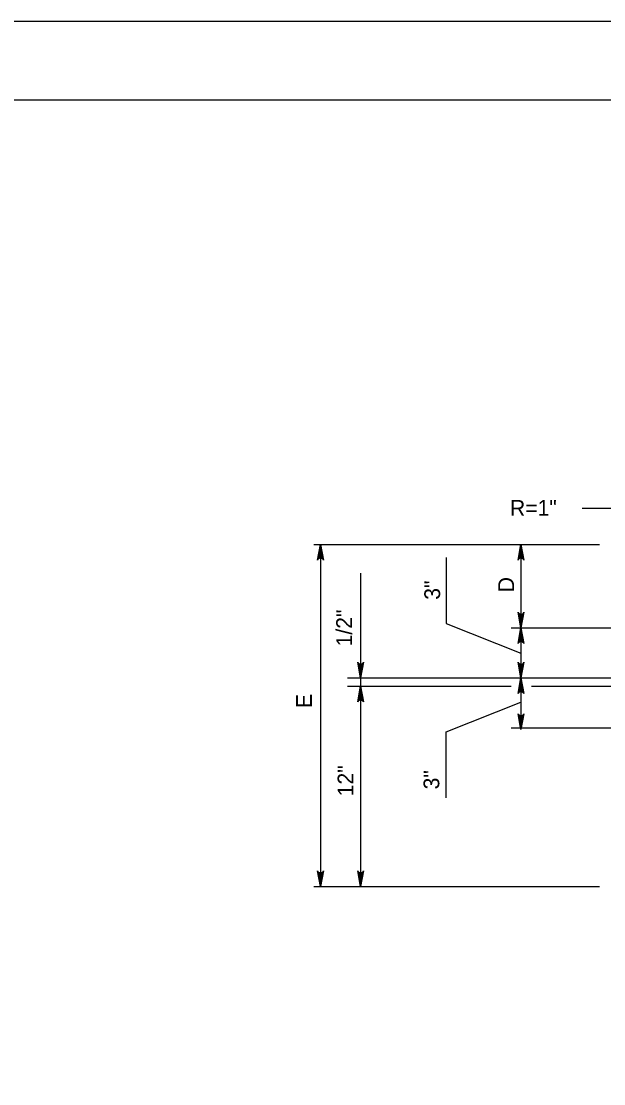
# Model space of a CAD drawing. Extents: x 2087776 to 2104538, y 970919 to 982612.
# Drawn here: x 2097196 to 2097559, y 981949 to 982612 of the extents above; entities that cross this region are included whole.
import ezdxf

# ---------------------------------------------------------------- set-up
doc = ezdxf.new("R2010")
doc.units = 0
doc.layers.add('1', color=7, linetype='Continuous')
doc.layers.add('PLT-BNDY', color=7, linetype='Continuous')

msp = doc.modelspace()

# ---------------------------------------------------------------- linework, layer by layer
at = {"layer": '1'}
for p, q in [((2097545.62, 982308.27), (2097566.97, 982308.27)), ((2097378.21, 982285.66), (2097556.45, 982285.66)), ((2097382.47, 982285.66), (2097382.47, 982072.11)), ((2097507.47, 982285.66), (2097507.47, 982171.07)), ((2097460.85, 982277.54), (2097460.85, 982236.2)), ((2097407.47, 982267.75), (2097407.47, 982072.11)), ((2097460.85, 982236.2), (2097507.47, 982217.8)), ((2097501.46, 982233.57), (2097633.63, 982233.57)), ((2097399.23, 982202.32), (2097633.63, 982202.32)), ((2097399.23, 982197.11), (2097501.46, 982197.11)), ((2097514.13, 982197.11), (2097633.63, 982197.11)), ((2097460.85, 982168.72), (2097507.47, 982187.12)), ((2097460.85, 982127.37), (2097460.85, 982168.72)), ((2097501.46, 982171.07), (2097607.78, 982171.07)), ((2097378.21, 982072.11), (2097556.45, 982072.11))]:
    msp.add_line(p, q, dxfattribs=at)
for points in [[(2098759.93, 980712.64), (2098759.93, 982563.04), (2096181.19, 982563.04), (2096181.19, 980712.64), (2098759.93, 980712.64), (2098759.93, 980799.12), (2098103.76, 980799.12), (2098103.76, 981011.32), (2098759.93, 981011.32), (2098759.93, 981106.34), (2098103.76, 981106.34), (2098103.76, 980712.64), (2098362.29, 980712.64), (2098362.29, 980799.12), (2098362.29, 980712.64), (2098614.92, 980712.64), (2098614.92, 980799.12), (2098614.92, 980758.72), (2098759.93, 980758.72)], [(2097382.47, 982285.66), (2097384.3, 982275.88), (2097384.04, 982276.25), (2097383.78, 982276.63), (2097383.45, 982276.82), (2097383.12, 982277.02), (2097382.8, 982277.07), (2097382.47, 982277.13), (2097382.14, 982277.07), (2097381.81, 982277.02), (2097381.48, 982276.82), (2097381.16, 982276.63), (2097380.89, 982276.25), (2097380.63, 982275.88), (2097382.47, 982285.66), (2097380.89, 982276.25), (2097381.16, 982276.63), (2097382.47, 982285.66), (2097381.48, 982276.82), (2097381.81, 982277.02), (2097382.47, 982285.66), (2097382.14, 982277.07), (2097382.47, 982277.13), (2097382.47, 982285.66), (2097382.8, 982277.07), (2097383.12, 982277.02), (2097382.47, 982285.66), (2097383.45, 982276.82), (2097383.78, 982276.63), (2097382.47, 982285.66), (2097384.04, 982276.25)], [(2097507.47, 982285.66), (2097509.3, 982275.88), (2097509.04, 982276.25), (2097508.78, 982276.63), (2097508.45, 982276.82), (2097508.12, 982277.02), (2097507.8, 982277.07), (2097507.47, 982277.13), (2097507.14, 982277.07), (2097506.81, 982277.02), (2097506.48, 982276.82), (2097506.16, 982276.63), (2097505.89, 982276.25), (2097505.63, 982275.88), (2097507.47, 982285.66), (2097505.89, 982276.25), (2097506.16, 982276.63), (2097507.47, 982285.66), (2097506.48, 982276.82), (2097506.81, 982277.02), (2097507.47, 982285.66), (2097507.14, 982277.07), (2097507.47, 982277.13), (2097507.47, 982285.66), (2097507.8, 982277.07), (2097508.12, 982277.02), (2097507.47, 982285.66), (2097508.45, 982276.82), (2097508.78, 982276.63), (2097507.47, 982285.66), (2097509.04, 982276.25)], [(2097507.47, 982233.57), (2097505.63, 982243.36), (2097505.89, 982242.98), (2097506.16, 982242.6), (2097506.48, 982242.41), (2097506.81, 982242.22), (2097507.14, 982242.16), (2097507.47, 982242.1), (2097507.8, 982242.16), (2097508.12, 982242.22), (2097508.45, 982242.41), (2097508.78, 982242.6), (2097509.04, 982242.98), (2097509.3, 982243.36), (2097507.47, 982233.57), (2097509.04, 982242.98), (2097508.78, 982242.6), (2097507.47, 982233.57), (2097508.45, 982242.41), (2097508.12, 982242.22), (2097507.47, 982233.57), (2097507.8, 982242.16), (2097507.47, 982242.1), (2097507.47, 982233.57), (2097507.14, 982242.16), (2097506.81, 982242.22), (2097507.47, 982233.57), (2097506.48, 982242.41), (2097506.16, 982242.6), (2097507.47, 982233.57), (2097505.89, 982242.98)], [(2097507.47, 982233.57), (2097509.3, 982223.79), (2097509.04, 982224.16), (2097508.78, 982224.54), (2097508.45, 982224.74), (2097508.12, 982224.93), (2097507.8, 982224.99), (2097507.47, 982225.04), (2097507.14, 982224.99), (2097506.81, 982224.93), (2097506.48, 982224.74), (2097506.16, 982224.54), (2097505.89, 982224.16), (2097505.63, 982223.79), (2097507.47, 982233.57), (2097505.89, 982224.16), (2097506.16, 982224.54), (2097507.47, 982233.57), (2097506.48, 982224.74), (2097506.81, 982224.93), (2097507.47, 982233.57), (2097507.14, 982224.99), (2097507.47, 982225.04), (2097507.47, 982233.57), (2097507.8, 982224.99), (2097508.12, 982224.93), (2097507.47, 982233.57), (2097508.45, 982224.74), (2097508.78, 982224.54), (2097507.47, 982233.57), (2097509.04, 982224.16)], [(2097407.47, 982202.32), (2097405.63, 982212.11), (2097405.89, 982211.73), (2097406.16, 982211.35), (2097406.48, 982211.16), (2097406.81, 982210.97), (2097407.14, 982210.91), (2097407.47, 982210.85), (2097407.8, 982210.91), (2097408.12, 982210.97), (2097408.45, 982211.16), (2097408.78, 982211.35), (2097409.04, 982211.73), (2097409.3, 982212.11), (2097407.47, 982202.32), (2097409.04, 982211.73), (2097408.78, 982211.35), (2097407.47, 982202.32), (2097408.45, 982211.16), (2097408.12, 982210.97), (2097407.47, 982202.32), (2097407.8, 982210.91), (2097407.47, 982210.85), (2097407.47, 982202.32), (2097407.14, 982210.91), (2097406.81, 982210.97), (2097407.47, 982202.32), (2097406.48, 982211.16), (2097406.16, 982211.35), (2097407.47, 982202.32), (2097405.89, 982211.73)], [(2097507.47, 982202.32), (2097505.63, 982212.11), (2097505.89, 982211.73), (2097506.16, 982211.35), (2097506.48, 982211.16), (2097506.81, 982210.97), (2097507.14, 982210.91), (2097507.47, 982210.85), (2097507.8, 982210.91), (2097508.12, 982210.97), (2097508.45, 982211.16), (2097508.78, 982211.35), (2097509.04, 982211.73), (2097509.3, 982212.11), (2097507.47, 982202.32), (2097509.04, 982211.73), (2097508.78, 982211.35), (2097507.47, 982202.32), (2097508.45, 982211.16), (2097508.12, 982210.97), (2097507.47, 982202.32), (2097507.8, 982210.91), (2097507.47, 982210.85), (2097507.47, 982202.32), (2097507.14, 982210.91), (2097506.81, 982210.97), (2097507.47, 982202.32), (2097506.48, 982211.16), (2097506.16, 982211.35), (2097507.47, 982202.32), (2097505.89, 982211.73)], [(2097507.47, 982202.32), (2097509.3, 982192.54), (2097509.04, 982192.91), (2097508.78, 982193.29), (2097508.45, 982193.49), (2097508.12, 982193.68), (2097507.8, 982193.74), (2097507.47, 982193.79), (2097507.14, 982193.74), (2097506.81, 982193.68), (2097506.48, 982193.49), (2097506.16, 982193.29), (2097505.89, 982192.91), (2097505.63, 982192.54), (2097507.47, 982202.32), (2097505.89, 982192.91), (2097506.16, 982193.29), (2097507.47, 982202.32), (2097506.48, 982193.49), (2097506.81, 982193.68), (2097507.47, 982202.32), (2097507.14, 982193.74), (2097507.47, 982193.79), (2097507.47, 982202.32), (2097507.8, 982193.74), (2097508.12, 982193.68), (2097507.47, 982202.32), (2097508.45, 982193.49), (2097508.78, 982193.29), (2097507.47, 982202.32), (2097509.04, 982192.91)], [(2097407.47, 982197.11), (2097409.3, 982187.33), (2097409.04, 982187.7), (2097408.78, 982188.08), (2097408.45, 982188.27), (2097408.12, 982188.47), (2097407.8, 982188.52), (2097407.47, 982188.58), (2097407.14, 982188.52), (2097406.81, 982188.47), (2097406.48, 982188.27), (2097406.16, 982188.08), (2097405.89, 982187.7), (2097405.63, 982187.33), (2097407.47, 982197.11), (2097405.89, 982187.7), (2097406.16, 982188.08), (2097407.47, 982197.11), (2097406.48, 982188.27), (2097406.81, 982188.47), (2097407.47, 982197.11), (2097407.14, 982188.52), (2097407.47, 982188.58), (2097407.47, 982197.11), (2097407.8, 982188.52), (2097408.12, 982188.47), (2097407.47, 982197.11), (2097408.45, 982188.27), (2097408.78, 982188.08), (2097407.47, 982197.11), (2097409.04, 982187.7)], [(2097507.47, 982170.16), (2097505.63, 982179.94), (2097505.89, 982179.57), (2097506.16, 982179.19), (2097506.48, 982178.99), (2097506.81, 982178.8), (2097507.14, 982178.74), (2097507.47, 982178.69), (2097507.8, 982178.74), (2097508.12, 982178.8), (2097508.45, 982178.99), (2097508.78, 982179.19), (2097509.04, 982179.57), (2097509.3, 982179.94), (2097507.47, 982170.16), (2097509.04, 982179.57), (2097508.78, 982179.19), (2097507.47, 982170.16), (2097508.45, 982178.99), (2097508.12, 982178.8), (2097507.47, 982170.16), (2097507.8, 982178.74), (2097507.47, 982178.69), (2097507.47, 982170.16), (2097507.14, 982178.74), (2097506.81, 982178.8), (2097507.47, 982170.16), (2097506.48, 982178.99), (2097506.16, 982179.19), (2097507.47, 982170.16), (2097505.89, 982179.57)], [(2097382.47, 982072.11), (2097380.63, 982081.9), (2097380.89, 982081.52), (2097381.16, 982081.14), (2097381.48, 982080.95), (2097381.81, 982080.75), (2097382.14, 982080.7), (2097382.47, 982080.64), (2097382.8, 982080.7), (2097383.12, 982080.75), (2097383.45, 982080.95), (2097383.78, 982081.14), (2097384.04, 982081.52), (2097384.3, 982081.9), (2097382.47, 982072.11), (2097384.04, 982081.52), (2097383.78, 982081.14), (2097382.47, 982072.11), (2097383.45, 982080.95), (2097383.12, 982080.75), (2097382.47, 982072.11), (2097382.8, 982080.7), (2097382.47, 982080.64), (2097382.47, 982072.11), (2097382.14, 982080.7), (2097381.81, 982080.75), (2097382.47, 982072.11), (2097381.48, 982080.95), (2097381.16, 982081.14), (2097382.47, 982072.11), (2097380.89, 982081.52)], [(2097407.47, 982072.11), (2097405.63, 982081.9), (2097405.89, 982081.52), (2097406.16, 982081.14), (2097406.48, 982080.95), (2097406.81, 982080.75), (2097407.14, 982080.7), (2097407.47, 982080.64), (2097407.8, 982080.7), (2097408.12, 982080.75), (2097408.45, 982080.95), (2097408.78, 982081.14), (2097409.04, 982081.52), (2097409.3, 982081.9), (2097407.47, 982072.11), (2097409.04, 982081.52), (2097408.78, 982081.14), (2097407.47, 982072.11), (2097408.45, 982080.95), (2097408.12, 982080.75), (2097407.47, 982072.11), (2097407.8, 982080.7), (2097407.47, 982080.64), (2097407.47, 982072.11), (2097407.14, 982080.7), (2097406.81, 982080.75), (2097407.47, 982072.11), (2097406.48, 982080.95), (2097406.16, 982081.14), (2097407.47, 982072.11), (2097405.89, 982081.52)]]:
    msp.add_lwpolyline(points, dxfattribs=at)
at = {"layer": 'PLT-BNDY'}
msp.add_lwpolyline([(2096053.23, 982612.25), (2098812.42, 982612.25), (2098812.42, 980663.43), (2096053.23, 980663.43)], close=True, dxfattribs=at)

# ---------------------------------------------------------------- texts
at = {"layer": '1'}
msp.add_text('R=1"', height=9.843, dxfattribs=at).set_placement((2097500.63, 982303.54))
for s, height, p in [('3"', 9.843, (2097457.04, 982251.14)), ('D', 9.84, (2097503.14, 982255.8)), ('1/2"', 9.843, (2097402.1, 982222.04)), ('E', 9.84, (2097377.07, 982183.58)), ('12"', 9.843, (2097402.97, 982128.45)), ('3"', 9.843, (2097456.55, 982132.75))]:
    msp.add_text(s, height=height, rotation=90, dxfattribs=at).set_placement(p)

doc.saveas('drawing.dxf')
